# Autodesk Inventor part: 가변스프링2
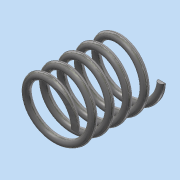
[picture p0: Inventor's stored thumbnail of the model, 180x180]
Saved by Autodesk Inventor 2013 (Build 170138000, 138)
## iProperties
Created: 2018-10
Part Number: 가변스프링2
Material: 스테인리스강
Document SubType Name: Modeling
Designer: Administrator
Density: 8.08 g/cm^3
Mass: 6.26686 g
Surface Area: 15.7589 cm^2
Volume: 0.775602 cm^3
Author: Administrator
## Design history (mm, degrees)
sketch "스케치1"
  geometry: L1 (0, 0)-(0, 24.5); L2 (0, 0)-(8, 0); L3 (0, 24.5)-(8, 24.5); C1 r 1 at (8, 0)
  constraints: 6 end point, 1 centre point, 1 coincident, 1 parallel, 1 perpendicular, 1 vertical
  dimensions: "d0" = 24.5 distance of L1.start L1.end (derived); "d1" = 8 distance of L1.start L2.end; "d2" = 2 diameter of C1; "d3" = 8 distance of L1.end L3.end
feature "코일1" sketch "스케치1" pitch "d4" = 24.5 (= d0); turns "d6" = 5; dims "d5" = 24.5 (= d0), "d7" = 0, angle "d8" = 90 deg, angle "d9" = 90 deg, "d10" = 0, "d11" = 0
sketch "스케치2"
  geometry: L1 (24.5, 11)-(0, 11); L2 (0, 11)-(0, -11); L3 (0, -11)-(24.5, -11); L4 (24.5, -11)-(24.5, 11); 2 further points
  constraints: 8 end point, 2 parallel, 1 coincident, 1 horizontal, 1 midpoint, 1 perpendicular
  dimensions: "d12" = 24.5 distance of L2.end L3.end (derived); "d16" = 22 distance of L3.end L1.start
extrude "돌출1" sketch "스케치2" stored distance "d14" = 0; taper "d15" = 0 deg
node "솔리드1"
